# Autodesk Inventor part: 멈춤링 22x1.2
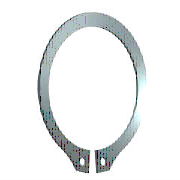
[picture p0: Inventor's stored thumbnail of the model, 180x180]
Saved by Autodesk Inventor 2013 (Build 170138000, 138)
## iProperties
IsCustomPart: 0
Created: 2015-11
Part Number: 멈춤링 22x1.2
Material: 스테인리스강
Description: 리테이닝 링(C형)
Document SubType Name: Modeling
Standard: KS B 1336
Designer: mdu
Standards Organization: KS
Language: ko-KR
Size Designation: 22 x 1.2
Categories: <MemberInstance><Categories><Category DisplayName="샤프트 부품" InternalName="7f7aeb1f-a693-4053-b835-cee3144e0d98" Mnemonic="SHFT"><Category DisplayName="써클립" Inter
Density: 8.08 g/cm^3
Mass: 1.87977 g
Surface Area: 5.91219 cm^2
Volume: 0.232645 cm^3
Author: mdu
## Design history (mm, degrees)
sketch "스케치1"
  geometry: L1 (-6, 0)-(6, 0) reference; L2 (0, 20.189)-(0, -80.536) reference; L3 (-48.09, 0)-(48.09, 0) reference; L4 (-0.5, -21.488)-(-0.5, -25.588); L5 (-0.5, -6.54)-(-0.5, -13.29); L6 (-2.795, 2.7)-(3.672, 2.7); L7 (0.5, -6.54)-(0.5, -13.29); L8 (0.5, -21.488)-(0.5, -25.588); C1 r 1 at (-2, -23.437); C2 r 1 at (2, -23.437); A1 r 10.5 centre (0, -11) between (0.5, -21.488) and (-0.5, -21.488); A2 r 13.025 centre (0, -10.325) between (5.149, -22.289) and (-5.149, -22.289); A3 r 14.597 centre (0, -11) between (-2.318, -25.411) and (-0.5, -25.588); A4 r 2 centre (-2, -23.437) between (-3.97, -23.781) and (-2.318, -25.411); A5 r 2 centre (-5.94, -24.126) between (-3.97, -23.781) and (-5.149, -22.289); A6 r 2 centre (5.94, -24.126) between (5.149, -22.289) and (3.97, -23.781); A7 r 2 centre (2, -23.437) between (2.318, -25.411) and (3.97, -23.781); A8 r 14.597 centre (0, -11) between (0.5, -25.588) and (2.318, -25.411)
  constraints: 16 point on circle, 12 end point, 10 centre point, 9 symmetric about line, 5 point on line, 4 tangent, 3 coincident, 2 horizontal, 1 perpendicular, 1 vertical, 5 other
  dimensions: "d0" = 21 diameter of A1 (= ND); "d1" = 4.1 distance of L4.end L4.start (= SRB2); "d6" = 0.5 distance between parallel lines of L2 L5 (= 0.25 x SD5); "d7" = 2.7 distance between parallel lines of L6 L3 (= SRB1); "d8" = 0.675 distance of A1.centre A2.centre (= 0.25 x SRB1); "d9" = 2 radius of A4 (= SD5); "d10" = 2 radius of A5 (= SD5); "d11" = 1.5 distance from line of L4 A4.centre (= 0.75 x SD5); "d12" = 2 diameter of C1 (= SD5); "d13" = 2 diameter of C2 (= SD5); "d14" = 11 distance from line of A1.centre L1 (= 0.5 x WD)
extrude "본체" new body sketch "스케치1" distance "d2" = 1.2 (= SD); taper "d3" = 0 deg
workaxis "Work Axis1"
workplane "Work Plane1"
body "Solid1"
other parameters: "WD" = 22 (= WDMIN) [user parameter; used in 1 equation term], "SD" = 1.2 [user parameter; used in 1 equation term], "SRB1" = 2.7 [user parameter; used in 2 equation terms], "ND" = 21 [user parameter; used in 1 equation term], "SRB2" = 4.1 [user parameter; used in 1 equation term], "SD5" = 2 [user parameter; used in 6 equation terms], "d15" = 0, "d16" = 0, "d17" = 0, "d41" = 0, "d42" = 0, "WDMIN" = 22 [user parameter; used in 1 equation term], "SD3" = 20.5 [user parameter], "WDMAX" = 24 [user parameter]
